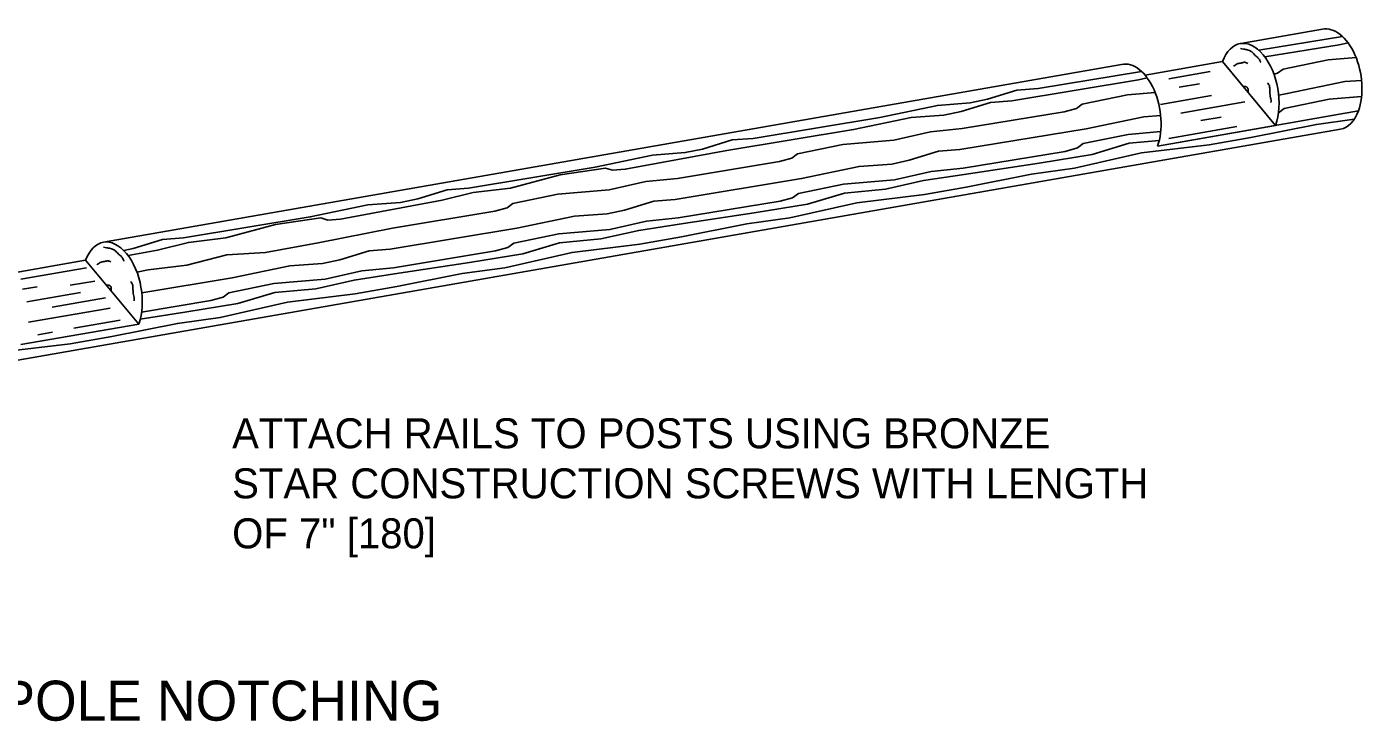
# Model space of a CAD drawing. Extents: x 49991 to 50288, y 49919 to 50011.
# Drawn here: x 50023.528 to 50026.32, y 49985.917 to 49987.366 of the extents above; entities that cross this region are included whole.
import ezdxf

# ---------------------------------------------------------------- set-up
doc = ezdxf.new("R2010")
doc.units = 0
doc.layers.add('Level 1', color=7, linetype='Continuous')
doc.layers.add('Level 2', color=7, linetype='Continuous')

msp = doc.modelspace()

# ---------------------------------------------------------------- linework, layer by layer
at = {"layer": 'Level 1'}
for p, q in [((50026.06226773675, 49987.33129291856), (50026.23272308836, 49987.36107245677)), ((50023.68792956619, 49986.916481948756), (50025.81341997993, 49987.287817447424)), ((50026.02394284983, 49987.293494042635), (50025.86245938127, 49987.26529953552)), ((50025.86249016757, 49987.26528850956), (50026.02394284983, 49987.293494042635)), ((50026.02396304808, 49987.29349756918), (50026.134829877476, 49987.160441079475)), ((50025.91238398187, 49987.25783010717), (50025.99852322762, 49987.27286951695)), ((50025.93388335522, 49987.24000767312), (50025.976141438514, 49987.24735626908)), ((50025.89470761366, 49987.20399729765), (50026.00093858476, 49987.22255088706)), ((50025.937501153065, 49987.1861553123), (50026.070551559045, 49987.20935680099)), ((50025.88857039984, 49987.11741086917), (50026.307902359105, 49987.190667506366)), ((50025.978847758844, 49987.170468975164), (50026.02110584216, 49987.177817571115)), ((50021.01237431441, 49986.23456588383), (50026.27076893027, 49987.15270974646)), ((50025.88856503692, 49987.117420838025), (50026.134829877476, 49987.160441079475)), ((50025.912314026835, 49987.13343477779), (50026.05394392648, 49987.15817170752)), ((50023.65085953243, 49986.878920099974), (50023.48937606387, 49986.850725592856)), ((50023.65298090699, 49986.863473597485), (50023.51549670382, 49986.839411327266)), ((50023.65087973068, 49986.87892362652), (50023.76174656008, 49986.745867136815)), ((50023.670125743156, 49986.83556709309), (50023.618906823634, 49986.82666106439)), ((50023.549503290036, 49986.82367427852), (50023.51885112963, 49986.81836657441)), ((50023.64021532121, 49986.811507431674), (50023.52844773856, 49986.79203031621)), ((50023.702129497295, 49986.77923285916), (50023.53199044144, 49986.74951559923)), ((50023.69223435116, 49986.800658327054), (50023.58081576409, 49986.781148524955)), ((50023.72310087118, 49986.75383325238), (50023.62634352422, 49986.73689062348)), ((50023.51548171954, 49986.702846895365), (50023.76174656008, 49986.745867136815)), ((50023.58212200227, 49986.728818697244), (50023.55150759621, 49986.72348037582))]:
    msp.add_line(p, q, dxfattribs=at)
for points in [[(50026.09984753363, 49987.317467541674), (50026.27448706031, 49987.34628529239)], [(50026.11275629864, 49987.30324433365), (50026.26797899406, 49987.328845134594), (50026.28637270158, 49987.332734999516)], [(50026.13167350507, 49987.26716352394), (50026.138946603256, 49987.269171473), (50026.15086439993, 49987.278156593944), (50026.24499528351, 49987.29741693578), (50026.302856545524, 49987.30228183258)], [(50025.58436738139, 49987.21200098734), (50025.84864703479, 49987.255588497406), (50025.867040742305, 49987.25947836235)], [(50025.63911962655, 49987.2373800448), (50025.85515510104, 49987.273028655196)], [(50026.14142430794, 49987.22387431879), (50026.15919640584, 49987.22680863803), (50026.27950730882, 49987.25184293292), (50026.314442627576, 49987.254522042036)], [(50025.044542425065, 49987.13343001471), (50025.30884199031, 49987.177157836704), (50025.429053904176, 49987.20214724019), (50025.49731423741, 49987.20737192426), (50025.5334934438, 49987.215019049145), (50025.59472759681, 49987.2339211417), (50025.63911962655, 49987.2373800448)], [(50025.48069976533, 49987.15366182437), (50025.69385085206, 49987.18880199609), (50025.71961464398, 49987.195914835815), (50025.731532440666, 49987.204899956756), (50025.82566332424, 49987.22416029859), (50025.88352458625, 49987.22902519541)], [(50024.989783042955, 49987.10811932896), (50025.25405199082, 49987.15180939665), (50025.37426390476, 49987.17679880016), (50025.44256556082, 49987.181958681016), (50025.478710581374, 49987.18960223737), (50025.54004372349, 49987.208549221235), (50025.58436738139, 49987.21200098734)], [(50026.14109463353, 49987.18701805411), (50026.15265495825, 49987.19578355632), (50026.246861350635, 49987.21498266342), (50026.31455678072, 49987.22071000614)], [(50025.47579347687, 49987.10995171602), (50025.73986444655, 49987.15355200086), (50025.860175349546, 49987.178586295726), (50025.8951106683, 49987.18126540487)], [(50026.08364640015, 49987.13538858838), (50026.220241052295, 49987.16267560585), (50026.29932952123, 49987.1734195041)], [(50024.886309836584, 49987.049904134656), (50025.099464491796, 49987.085010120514), (50025.12511858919, 49987.092180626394), (50025.13714251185, 49987.10114226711), (50025.23126982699, 49987.12043679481), (50025.33801781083, 49987.12940256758), (50025.41453583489, 49987.14689349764), (50025.48069976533, 49987.15366182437)], [(50025.482497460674, 49987.071220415), (50025.69551537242, 49987.106312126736), (50025.72137815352, 49987.11346985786), (50025.73332299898, 49987.12252691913), (50025.82752939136, 49987.141726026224), (50025.89522482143, 49987.147453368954)], [(50024.45004280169, 49987.0297299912), (50024.71435664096, 49987.07332106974), (50024.83455784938, 49987.09841303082), (50024.902756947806, 49987.103562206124), (50024.938943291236, 49987.11114095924), (50025.00027643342, 49987.13008794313), (50025.044542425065, 49987.13343001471)], [(50025.48470250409, 49987.058041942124), (50025.64131274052, 49987.08195807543), (50025.7522837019, 49987.0997969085), (50025.82923492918, 49987.12306974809), (50025.89205568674, 49987.12889273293)], [(50025.48927074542, 49987.03149415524), (50025.62576284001, 49987.05877046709), (50025.715190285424, 49987.071111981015), (50025.85539421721, 49987.10288820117), (50025.99662189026, 49987.12022221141), (50026.08364640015, 49987.13538858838)], [(50024.989783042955, 49987.10811932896), (50024.7773948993, 49987.06898090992), (50024.75062436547, 49987.0668776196), (50024.736460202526, 49987.07113577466), (50024.64134098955, 49987.057370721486), (50024.53782056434, 49987.02973475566), (50024.4599133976, 49987.02025459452), (50024.39544871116, 49987.0041600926)], [(50024.88127751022, 49987.006077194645), (50025.145564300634, 49987.04959633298), (50025.265693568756, 49987.07471534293), (50025.33396460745, 49987.07983746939), (50025.37012953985, 49987.087621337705), (50025.43157951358, 49987.1064422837), (50025.47579347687, 49987.10995171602)], [(50024.88801924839, 49986.96731527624), (50025.10104072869, 49987.00237280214), (50025.126862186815, 49987.00959533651), (50025.13892386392, 49987.018526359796), (50025.23300985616, 49987.03788569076), (50025.339720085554, 49987.04688208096), (50025.41620035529, 49987.06440362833), (50025.482497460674, 49987.071220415)], [(50024.890220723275, 49986.954170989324), (50025.046762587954, 49986.97807998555), (50025.15786315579, 49986.996001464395), (50025.234916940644, 49987.019285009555), (50025.320636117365, 49987.027092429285), (50025.400062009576, 49987.04519792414), (50025.48470250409, 49987.058041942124)], [(50023.855533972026, 49986.92578709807), (50024.11981005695, 49986.96940879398), (50024.24000412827, 49986.99456912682), (50024.30821393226, 49986.99961574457), (50024.34445437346, 49987.00733837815), (50024.40572271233, 49987.02624403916), (50024.45004280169, 49987.0297299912)], [(50024.291885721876, 49986.94614287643), (50024.505016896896, 49986.98114273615), (50024.530827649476, 49986.98846782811), (50024.542721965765, 49986.997346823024), (50024.636879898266, 49987.016679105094), (50024.743624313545, 49987.02567906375), (50024.82014947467, 49987.04310162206), (50024.886309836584, 49987.049904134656)], [(50024.894887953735, 49986.92766809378), (50025.03141780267, 49986.9549137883), (50025.12077687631, 49986.96724816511), (50025.26096653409, 49986.99916112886), (50025.402102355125, 49987.016381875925), (50025.48927074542, 49987.03149415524)], [(50024.39544871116, 49987.0041600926), (50024.18288963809, 49986.965003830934), (50024.156218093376, 49986.962945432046), (50024.142122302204, 49986.96721072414), (50024.046976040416, 49986.95337373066), (50023.94341429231, 49986.92580256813), (50023.86562395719, 49986.91619636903), (50023.8011485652, 49986.90020442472)], [(50024.28666612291, 49986.902123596), (50024.55093150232, 49986.945847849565), (50024.67124597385, 49986.970847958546), (50024.73950987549, 49986.97603845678), (50024.77571256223, 49986.98379170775), (50024.83698803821, 49987.00262899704), (50024.88127751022, 49987.006077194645)], [(50024.291885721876, 49986.94614287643), (50024.13653616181, 49986.915446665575), (50024.026151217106, 49986.89497345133), (50023.94588264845, 49986.89056878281), (50023.8623715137, 49986.86889203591), (50023.78154220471, 49986.85893405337), (50023.757977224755, 49986.854262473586)], [(50024.29357165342, 49986.863447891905), (50024.5065859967, 49986.89857378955), (50024.532468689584, 49986.905871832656), (50024.54449974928, 49986.914765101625), (50024.63856226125, 49986.93401830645), (50024.74530310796, 49986.943052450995), (50024.82179408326, 49986.96047144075), (50024.88801924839, 49986.96731527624)], [(50024.29587568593, 49986.85031431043), (50024.452352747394, 49986.874181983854), (50024.563449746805, 49986.89213764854), (50024.64040811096, 49986.91534211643), (50024.72613292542, 49986.92342659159), (50024.805648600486, 49986.941334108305), (50024.890220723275, 49986.954170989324)], [(50023.73053339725, 49986.899330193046), (50023.749976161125, 49986.903433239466), (50023.81121031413, 49986.92233533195), (50023.855533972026, 49986.92578709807)], [(50024.300539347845, 49986.82384560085), (50024.436932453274, 49986.85107702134), (50024.526354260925, 49986.86314147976), (50024.66658374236, 49986.89533506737), (50024.80768537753, 49986.91255224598), (50024.894887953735, 49986.92766809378)], [(50023.8011485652, 49986.90020442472), (50023.73953957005, 49986.88886604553)], [(50023.768210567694, 49986.81085406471), (50023.9566512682, 49986.842032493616), (50024.076931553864, 49986.86702903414), (50024.145127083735, 49986.872212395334), (50024.18129558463, 49986.879962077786), (50024.242506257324, 49986.8987580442), (50024.28666612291, 49986.902123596)], [(50023.76781325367, 49986.77093594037), (50023.91230576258, 49986.79475843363), (50023.93809303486, 49986.80197739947), (50023.94999091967, 49986.8108222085), (50024.044145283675, 49986.83018867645), (50024.15085908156, 49986.83915088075), (50024.22744904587, 49986.85661476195), (50024.29357165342, 49986.863447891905)], [(50023.764929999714, 49986.75612178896), (50023.85790872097, 49986.77028041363), (50023.96898787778, 49986.78840700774), (50024.04589571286, 49986.81143340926), (50024.13181850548, 49986.81960766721), (50024.21130356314, 49986.837477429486), (50024.29587568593, 49986.85031431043)], [(50023.70588306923, 49986.71999099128), (50023.84251904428, 49986.74721320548), (50023.931994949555, 49986.75942154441), (50024.072215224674, 49986.79137226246), (50024.21334034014, 49986.80869556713), (50024.300539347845, 49986.82384560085)], [(50023.111541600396, 49986.61610012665), (50023.24813982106, 49986.64335295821), (50023.337355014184, 49986.655741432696), (50023.4776308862, 49986.68749060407), (50023.61869119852, 49986.70477258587), (50023.70588306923, 49986.71999099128)]]:
    msp.add_lwpolyline(points, dxfattribs=at)
for centre, start_param, end_param in [((50026.25241213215, 49987.257054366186), 3.9254893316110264, 6.306125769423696), ((50026.07934257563, 49987.22681006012), 3.9256121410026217, 7.063370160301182), ((50025.83308017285, 49987.183797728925), 3.9254893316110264, 6.306125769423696), ((50026.25238534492, 49987.25698116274), 3.1414661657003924, 3.926391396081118), ((50023.70625925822, 49986.81223611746), 3.9256121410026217, 7.063370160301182)]:
    msp.add_ellipse(centre, major_axis=(-0.01831237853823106, 0.10428811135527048), ratio=0.577493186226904, start_param=start_param, end_param=end_param, dxfattribs=at)
for points in [[(50026.06162831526, 49987.32085629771), (50026.067857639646, 49987.31977863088), (50026.0757344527, 49987.31814721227), (50026.080252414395, 49987.316579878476), (50026.08530193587, 49987.313893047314), (50026.08868498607, 49987.310617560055), (50026.09204605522, 49987.30689051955), (50026.097191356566, 49987.302624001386), (50026.09884691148, 49987.30099978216), (50026.10111817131, 49987.29778103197), (50026.10336331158, 49987.29348824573), (50026.10391064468, 49987.29188657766)], [(50026.04721024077, 49987.283891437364), (50026.04884020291, 49987.285047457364), (50026.056447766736, 49987.28951957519), (50026.06415957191, 49987.29097504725), (50026.07081994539, 49987.292212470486), (50026.07696974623, 49987.2898652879)], [(50026.067646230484, 49987.241071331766), (50026.06769560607, 49987.24111093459), (50026.06778206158, 49987.24117925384), (50026.068038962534, 49987.24135804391), (50026.06830582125, 49987.24150206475), (50026.06886454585, 49987.241696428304), (50026.06915439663, 49987.24175202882), (50026.069449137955, 49987.24178662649), (50026.07004795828, 49987.24178484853), (50026.07035454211, 49987.24175497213), (50026.070656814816, 49987.24171823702), (50026.07095627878, 49987.24167224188), (50026.07125443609, 49987.24161458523), (50026.071841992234, 49987.24148559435), (50026.07240611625, 49987.24135570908), (50026.07278449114, 49987.24126672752), (50026.07316052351, 49987.24116637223), (50026.073901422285, 49987.24090984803), (50026.07462053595, 49987.24054275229), (50026.07496933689, 49987.24030418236), (50026.075140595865, 49987.240168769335), (50026.075309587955, 49987.240021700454), (50026.07574034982, 49987.23960635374), (50026.076130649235, 49987.239179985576), (50026.07647095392, 49987.23874826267), (50026.076627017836, 49987.23852175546), (50026.07677531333, 49987.238287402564), (50026.07702178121, 49987.23782045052), (50026.07721448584, 49987.237330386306), (50026.077347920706, 49987.2368234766), (50026.077419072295, 49987.23629537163), (50026.07748560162, 49987.235045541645), (50026.07750838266, 49987.233801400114), (50026.077492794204, 49987.232559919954), (50026.0774442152, 49987.23131807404), (50026.0774076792, 49987.23056020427), (50026.07737168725, 49987.22980240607), (50026.07735226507, 49987.22942375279)], [(50026.12516043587, 49987.20849969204), (50026.12568027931, 49987.213242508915), (50026.12451613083, 49987.218227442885), (50026.12294589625, 49987.23029329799), (50026.12270817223, 49987.23349007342), (50026.12202909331, 49987.24277102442), (50026.118150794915, 49987.24909889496)], [(50023.68854499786, 49986.90628235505), (50023.69477432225, 49986.90520468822), (50023.7026511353, 49986.90357326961), (50023.707169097, 49986.902005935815), (50023.71221861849, 49986.89931910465), (50023.71560166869, 49986.896043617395), (50023.718962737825, 49986.89231657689), (50023.72410803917, 49986.888050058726), (50023.725763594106, 49986.8864258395), (50023.72803485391, 49986.883207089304), (50023.73027999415, 49986.878914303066), (50023.73082732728, 49986.87731263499)], [(50023.674126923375, 49986.869317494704), (50023.67575688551, 49986.870473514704), (50023.68336444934, 49986.87494563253), (50023.691076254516, 49986.87640110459), (50023.69773662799, 49986.877638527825), (50023.70388642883, 49986.87529134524)], [(50023.75207711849, 49986.79392574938), (50023.75259696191, 49986.798668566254), (50023.751432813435, 49986.803653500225), (50023.74986257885, 49986.81571935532), (50023.74962485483, 49986.81891613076), (50023.748945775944, 49986.82819708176), (50023.74506747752, 49986.8345249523)], [(50023.694562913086, 49986.826497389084), (50023.694612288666, 49986.82653699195), (50023.69469874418, 49986.82660531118), (50023.694955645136, 49986.82678410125), (50023.695222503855, 49986.82692812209), (50023.69578122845, 49986.82712248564), (50023.696071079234, 49986.82717808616), (50023.69636582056, 49986.82721268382), (50023.69696464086, 49986.82721090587), (50023.697271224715, 49986.82718102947), (50023.69757349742, 49986.82714429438), (50023.697872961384, 49986.82709829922), (50023.69817111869, 49986.82704064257), (50023.698758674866, 49986.82691165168), (50023.69932279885, 49986.82678176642), (50023.69970117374, 49986.82669278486), (50023.700077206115, 49986.82659242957), (50023.70081810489, 49986.82633590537), (50023.70153721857, 49986.82596880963), (50023.70188601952, 49986.8257302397), (50023.70205727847, 49986.8255948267), (50023.70222627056, 49986.825447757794), (50023.702657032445, 49986.82503241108), (50023.70304733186, 49986.824606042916), (50023.703387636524, 49986.82417432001), (50023.70354370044, 49986.8239478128), (50023.70369199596, 49986.8237134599), (50023.70393846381, 49986.82324650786), (50023.70413116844, 49986.822756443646), (50023.70426460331, 49986.82224953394), (50023.70433575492, 49986.82172142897), (50023.70440228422, 49986.820471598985), (50023.704425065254, 49986.819227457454), (50023.704409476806, 49986.81798597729), (50023.70436089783, 49986.81674413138), (50023.7043243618, 49986.81598626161), (50023.70428836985, 49986.81522846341), (50023.70426894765, 49986.81484981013)]]:
    msp.add_spline(points, degree=3, dxfattribs=at)

# ---------------------------------------------------------------- texts
at = {"layer": 'Level 2'}
for s, height, p in [('ATTACH RAILS TO POSTS USING BRONZE ', 0.06264226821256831, (50023.95676201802, 49986.48639956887)), ('STAR CONSTRUCTION SCREWS WITH LENGTH', 0.06264226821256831, (50023.95676201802, 49986.38199578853)), ('OF 7" [180]', 0.06264226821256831, (50023.95676201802, 49986.27759200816)), ('BRACE POLE NOTCHING', 0.08352302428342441, (50023.05499243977, 49985.917844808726))]:
    msp.add_text(s, height=height, dxfattribs=at).set_placement(p)

doc.saveas('drawing.dxf')
